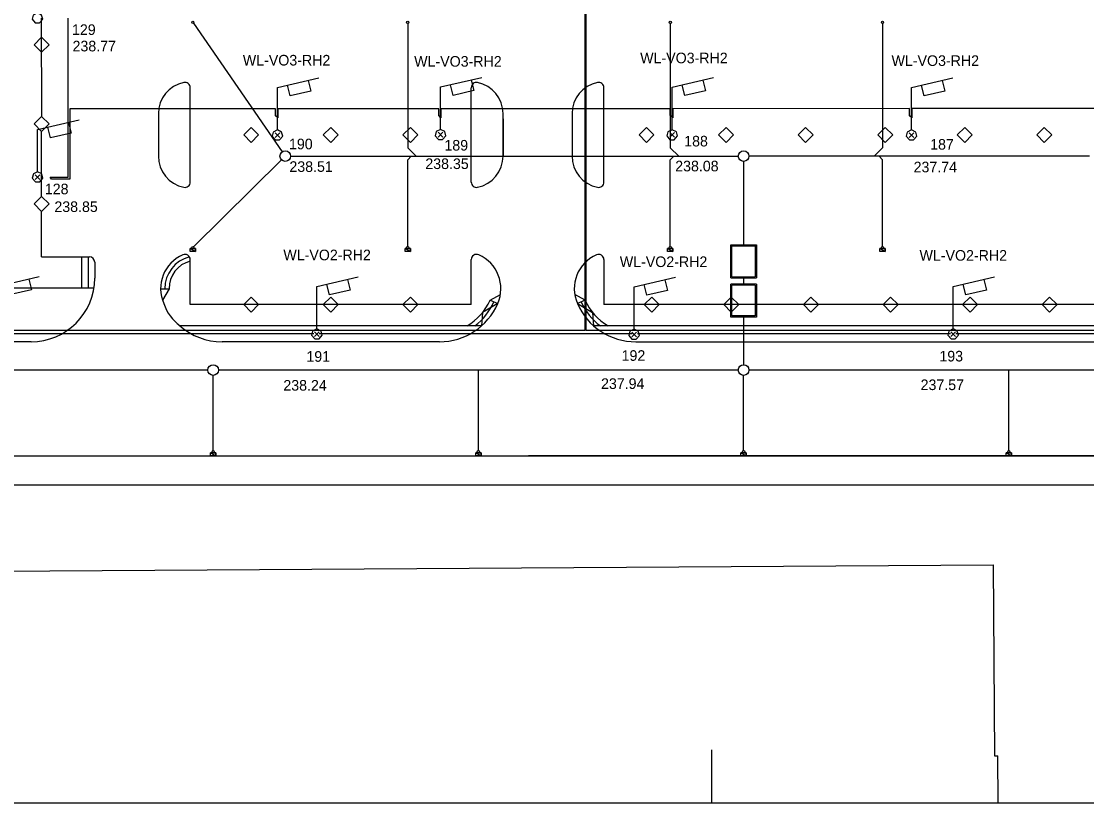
# Model space of a CAD drawing. Extents: x -264222 to -263592, y -1242345 to -1242048.
# Drawn here: x -263972 to -263871.6, y -1242344.9 to -1242271.3 of the extents above; entities that cross this region are included whole.
import ezdxf

# ---------------------------------------------------------------- set-up
doc = ezdxf.new("R2010")
doc.units = 0
for name, color, linetype in [('BOD_CISLO', 7, 'Continuous'), ('BOD_SYMBOL', 7, 'Continuous'), ('BOD_VYSKA', 7, 'Continuous'), ('KFA_2D_SITUACIA_DSP', 7, 'Continuous'), ('KFA_SO_62-1_VO_LAMPY_MERANE', 7, 'Continuous'), ('KFA_SO_62-1_VO_POPIS_LAMP_PROJEKT', 7, 'Continuous'), ('KFA_SO_62-1_VO_TRASA_KABLOV_PROJEKT', 7, 'Continuous'), ('RAM_NA_TLAC_1-500', 7, 'Continuous')]:
    doc.layers.add(name, color=color, linetype=linetype)

msp = doc.modelspace()

# ---------------------------------------------------------------- linework, layer by layer
at = {"layer": 'BOD_SYMBOL'}
for p, q in [((-263948.07, -1242282.23), (-263947.62, -1242281.78)), ((-263947.62, -1242282.23), (-263948.07, -1242281.78)), ((-263932.7, -1242282.19), (-263932.26, -1242281.74)), ((-263932.26, -1242282.19), (-263932.7, -1242281.74)), ((-263910.87, -1242282.21), (-263910.43, -1242281.76)), ((-263910.43, -1242282.21), (-263910.87, -1242281.76)), ((-263888.31, -1242282.23), (-263887.86, -1242281.79)), ((-263887.86, -1242282.23), (-263888.31, -1242281.79)), ((-263970.67, -1242286.19), (-263970.23, -1242285.74)), ((-263970.23, -1242286.19), (-263970.67, -1242285.74)), ((-263944.35, -1242300.99), (-263943.91, -1242300.55)), ((-263943.91, -1242300.99), (-263944.35, -1242300.55)), ((-263914.46, -1242301.01), (-263914.01, -1242300.57)), ((-263914.01, -1242301.01), (-263914.46, -1242300.57)), ((-263884.39, -1242300.99), (-263883.94, -1242300.55)), ((-263883.94, -1242300.99), (-263884.39, -1242300.55))]:
    msp.add_line(p, q, dxfattribs=at)
at = {"layer": 'KFA_2D_SITUACIA_DSP'}
for p, q in [((-263970.06, -1242280.24), (-263970.07, -1242270.98)), ((-263955.76, -1242271.45), (-263947.39, -1242283.57)), ((-263935.57, -1242271.47), (-263935.57, -1242283.19)), ((-263910.82, -1242271.47), (-263910.82, -1242283.19)), ((-263890.82, -1242271.47), (-263890.82, -1242283.19)), ((-263956.07, -1242286.43), (-263956.07, -1242277.53)), ((-263929.58, -1242286.43), (-263929.58, -1242277.53)), ((-263917.08, -1242286.43), (-263917.08, -1242277.53)), ((-263959.07, -1242279.98), (-263959.07, -1242283.98)), ((-263926.58, -1242283.98), (-263926.58, -1242279.98)), ((-263926.58, -1242280.48), (-263926.58, -1242283.98)), ((-263920.08, -1242279.98), (-263920.08, -1242283.98)), ((-263970.07, -1242287.78), (-263970.07, -1242281.65)), ((-263935.57, -1242283.19), (-263934.78, -1242283.98)), ((-263910.82, -1242283.19), (-263910.03, -1242283.98)), ((-263890.82, -1242283.19), (-263891.62, -1242283.98)), ((-263955.75, -1242292.52), (-263947.46, -1242284.33)), ((-263946.61, -1242283.98), (-263908.96, -1242283.98)), ((-263946.61, -1242283.98), (-263904.41, -1242283.98)), ((-263935.57, -1242284.34), (-263935.25, -1242283.98)), ((-263935.57, -1242292.49), (-263935.57, -1242284.34)), ((-263910.82, -1242284.34), (-263910.5, -1242283.98)), ((-263910.82, -1242292.49), (-263910.82, -1242284.34)), ((-263903.91, -1242284.48), (-263903.91, -1242292.35)), ((-263871.32, -1242283.98), (-263903.41, -1242283.98)), ((-263890.82, -1242284.34), (-263891.15, -1242283.98)), ((-263890.82, -1242292.49), (-263890.82, -1242284.34)), ((-263970.07, -1242293.48), (-263970.07, -1242289.19)), ((-263905.11, -1242292.35), (-263902.71, -1242292.35)), ((-263905.11, -1242295.45), (-263905.11, -1242292.35)), ((-263905.01, -1242292.45), (-263902.81, -1242292.45)), ((-263905.01, -1242295.35), (-263905.01, -1242292.45)), ((-263902.81, -1242292.45), (-263902.81, -1242295.35)), ((-263902.71, -1242292.35), (-263902.71, -1242295.45)), ((-263970.07, -1242293.48), (-263965.57, -1242293.48)), ((-263966.31, -1242293.48), (-263966.31, -1242296.43)), ((-263965.68, -1242293.48), (-263965.68, -1242296.43)), ((-263956.07, -1242292.69), (-263955.57, -1242292.69)), ((-263956.07, -1242292.98), (-263956.07, -1242292.69)), ((-263956.07, -1242292.69), (-263955.57, -1242292.98)), ((-263956.07, -1242292.69), (-263955.57, -1242292.98)), ((-263955.57, -1242292.69), (-263956.07, -1242292.69)), ((-263955.57, -1242292.98), (-263956.07, -1242292.98)), ((-263955.57, -1242292.69), (-263955.57, -1242292.98)), ((-263955.57, -1242292.98), (-263955.57, -1242292.69)), ((-263935.82, -1242292.69), (-263935.32, -1242292.69)), ((-263935.82, -1242292.98), (-263935.82, -1242292.69)), ((-263935.82, -1242292.69), (-263935.32, -1242292.98)), ((-263935.82, -1242292.69), (-263935.32, -1242292.98)), ((-263935.32, -1242292.69), (-263935.82, -1242292.69)), ((-263935.32, -1242292.98), (-263935.82, -1242292.98)), ((-263935.32, -1242292.69), (-263935.32, -1242292.98)), ((-263935.32, -1242292.98), (-263935.32, -1242292.69)), ((-263911.07, -1242292.69), (-263910.57, -1242292.69)), ((-263911.07, -1242292.98), (-263911.07, -1242292.69)), ((-263911.07, -1242292.69), (-263910.57, -1242292.98)), ((-263911.07, -1242292.69), (-263910.57, -1242292.98)), ((-263910.57, -1242292.69), (-263911.07, -1242292.69)), ((-263910.57, -1242292.98), (-263911.07, -1242292.98)), ((-263910.57, -1242292.69), (-263910.57, -1242292.98)), ((-263910.57, -1242292.98), (-263910.57, -1242292.69)), ((-263891.07, -1242292.69), (-263890.57, -1242292.69)), ((-263891.07, -1242292.98), (-263891.07, -1242292.69)), ((-263891.07, -1242292.69), (-263890.57, -1242292.98)), ((-263891.07, -1242292.69), (-263890.57, -1242292.98)), ((-263890.57, -1242292.69), (-263891.07, -1242292.69)), ((-263890.57, -1242292.98), (-263891.07, -1242292.98)), ((-263890.57, -1242292.69), (-263890.57, -1242292.98)), ((-263890.57, -1242292.98), (-263890.57, -1242292.69)), ((-263965.07, -1242293.98), (-263965.07, -1242295.48)), ((-263956.07, -1242297.98), (-263956.07, -1242293.74)), ((-263929.58, -1242297.98), (-263929.58, -1242293.74)), ((-263917.08, -1242293.74), (-263917.08, -1242297.98)), ((-263905.11, -1242295.45), (-263902.71, -1242295.45)), ((-263905.01, -1242295.35), (-263902.81, -1242295.35)), ((-263903.91, -1242295.45), (-263903.91, -1242296.05)), ((-263905.11, -1242299.15), (-263905.11, -1242296.05)), ((-263902.71, -1242296.05), (-263905.11, -1242296.05)), ((-263902.81, -1242296.15), (-263905.01, -1242296.15)), ((-263905.01, -1242299.05), (-263905.01, -1242296.15)), ((-263902.81, -1242296.15), (-263902.81, -1242299.05)), ((-263902.71, -1242296.05), (-263902.71, -1242299.15)), ((-263927.81, -1242297.56), (-263926.83, -1242297.03)), ((-263918.85, -1242297.56), (-263919.83, -1242297.03)), ((-263929.58, -1242297.98), (-263956.07, -1242297.98)), ((-263927.81, -1242297.56), (-263927.08, -1242297.88)), ((-263918.85, -1242297.56), (-263919.58, -1242297.88)), ((-263815.6, -1242297.98), (-263917.08, -1242297.98)), ((-263902.71, -1242299.15), (-263905.11, -1242299.15)), ((-263902.81, -1242299.05), (-263905.01, -1242299.05)), ((-263903.91, -1242299.15), (-263903.91, -1242303.65)), ((-263928.61, -1242299.98), (-263957.04, -1242299.98)), ((-263816.31, -1242299.98), (-263918.05, -1242299.98)), ((-263971.07, -1242301.48), (-264112.96, -1242301.48)), ((-263932.58, -1242301.48), (-263953.07, -1242301.48)), ((-263914.08, -1242301.48), (-263815.82, -1242301.48)), ((-263954.41, -1242304.15), (-264003.4, -1242304.15)), ((-263904.41, -1242304.15), (-263953.41, -1242304.15)), ((-263928.91, -1242311.74), (-263928.91, -1242304.15)), ((-263854.41, -1242304.15), (-263903.41, -1242304.15)), ((-263878.91, -1242311.74), (-263878.91, -1242304.15)), ((-263953.91, -1242311.74), (-263953.91, -1242304.65)), ((-263903.91, -1242311.74), (-263903.91, -1242304.65)), ((-263980.94, -1242312.23), (-263857.33, -1242312.23)), ((-263954.16, -1242311.94), (-263953.66, -1242311.94)), ((-263954.16, -1242312.23), (-263954.16, -1242311.94)), ((-263954.16, -1242311.94), (-263953.66, -1242312.23)), ((-263954.16, -1242311.94), (-263953.66, -1242312.23)), ((-263953.66, -1242311.94), (-263954.16, -1242311.94)), ((-263953.66, -1242312.23), (-263954.16, -1242312.23)), ((-263953.66, -1242311.94), (-263953.66, -1242312.23)), ((-263953.66, -1242312.23), (-263953.66, -1242311.94)), ((-263929.16, -1242311.94), (-263928.66, -1242311.94)), ((-263929.16, -1242312.23), (-263929.16, -1242311.94)), ((-263929.16, -1242311.94), (-263928.66, -1242312.23)), ((-263929.16, -1242311.94), (-263928.66, -1242312.23)), ((-263928.66, -1242311.94), (-263929.16, -1242311.94)), ((-263928.66, -1242312.23), (-263929.16, -1242312.23)), ((-263928.66, -1242311.94), (-263928.66, -1242312.23)), ((-263928.66, -1242312.23), (-263928.66, -1242311.94)), ((-263842.6, -1242312.24), (-263924.19, -1242312.23)), ((-263904.16, -1242311.94), (-263903.66, -1242311.94)), ((-263904.16, -1242312.23), (-263904.16, -1242311.94)), ((-263904.16, -1242311.94), (-263903.66, -1242312.23)), ((-263904.16, -1242311.94), (-263903.66, -1242312.23)), ((-263903.66, -1242311.94), (-263904.16, -1242311.94)), ((-263903.66, -1242312.23), (-263904.16, -1242312.23)), ((-263903.66, -1242311.94), (-263903.66, -1242312.23)), ((-263903.66, -1242312.23), (-263903.66, -1242311.94)), ((-263879.16, -1242311.94), (-263878.66, -1242311.94)), ((-263879.16, -1242312.23), (-263879.16, -1242311.94)), ((-263879.16, -1242311.94), (-263878.66, -1242312.23)), ((-263879.16, -1242311.94), (-263878.66, -1242312.23)), ((-263878.66, -1242311.94), (-263879.16, -1242311.94)), ((-263878.66, -1242312.23), (-263879.16, -1242312.23)), ((-263878.66, -1242311.94), (-263878.66, -1242312.23)), ((-263878.66, -1242312.23), (-263878.66, -1242311.94)), ((-264038.44, -1242314.98), (-263836.4, -1242314.98)), ((-263976.89, -1242323.14), (-263880.39, -1242322.51)), ((-263880.39, -1242322.51), (-263880.27, -1242340.53)), ((-263880.27, -1242340.53), (-263879.95, -1242340.53)), ((-263879.92, -1242344.94), (-263879.95, -1242340.53))]:
    msp.add_line(p, q, dxfattribs=at)
for points in [[(-263970.07, -1242272.78), (-263969.36, -1242273.48), (-263970.07, -1242274.19), (-263970.77, -1242273.48)], [(-263970.07, -1242280.24), (-263969.36, -1242280.94), (-263970.07, -1242281.65), (-263970.77, -1242280.94)], [(-263950.32, -1242281.28), (-263949.62, -1242281.98), (-263950.32, -1242282.69), (-263951.03, -1242281.98)], [(-263942.82, -1242281.28), (-263942.12, -1242281.98), (-263942.82, -1242282.69), (-263943.53, -1242281.98)], [(-263935.32, -1242281.28), (-263934.62, -1242281.98), (-263935.32, -1242282.69), (-263936.03, -1242281.98)], [(-263913.07, -1242281.28), (-263912.36, -1242281.98), (-263913.07, -1242282.69), (-263913.77, -1242281.98)], [(-263905.57, -1242281.28), (-263904.86, -1242281.98), (-263905.57, -1242282.69), (-263906.27, -1242281.98)], [(-263898.07, -1242281.28), (-263897.36, -1242281.98), (-263898.07, -1242282.69), (-263898.77, -1242281.98)], [(-263890.57, -1242281.28), (-263889.86, -1242281.98), (-263890.57, -1242282.69), (-263891.27, -1242281.98)], [(-263890.57, -1242281.28), (-263889.86, -1242281.98), (-263890.57, -1242282.69), (-263891.27, -1242281.98)], [(-263883.07, -1242281.28), (-263882.36, -1242281.98), (-263883.07, -1242282.69), (-263883.77, -1242281.98)], [(-263875.57, -1242281.28), (-263874.86, -1242281.98), (-263875.57, -1242282.69), (-263876.27, -1242281.98)], [(-263970.07, -1242287.78), (-263969.36, -1242288.48), (-263970.07, -1242289.19), (-263970.77, -1242288.48)], [(-263949.62, -1242297.98), (-263950.32, -1242297.28), (-263951.03, -1242297.98), (-263950.32, -1242298.69)], [(-263942.12, -1242297.98), (-263942.82, -1242297.28), (-263943.53, -1242297.98), (-263942.82, -1242298.69)], [(-263934.62, -1242297.98), (-263935.32, -1242297.28), (-263936.03, -1242297.98), (-263935.32, -1242298.69)], [(-263912.57, -1242297.28), (-263911.86, -1242297.98), (-263912.57, -1242298.69), (-263913.27, -1242297.98)], [(-263905.07, -1242297.28), (-263904.36, -1242297.98), (-263905.07, -1242298.69), (-263905.77, -1242297.98)], [(-263897.57, -1242297.28), (-263896.86, -1242297.98), (-263897.57, -1242298.69), (-263898.27, -1242297.98)], [(-263890.07, -1242297.28), (-263889.36, -1242297.98), (-263890.07, -1242298.69), (-263890.77, -1242297.98)], [(-263890.07, -1242297.28), (-263889.36, -1242297.98), (-263890.07, -1242298.69), (-263890.77, -1242297.98)], [(-263882.57, -1242297.28), (-263881.86, -1242297.98), (-263882.57, -1242298.69), (-263883.27, -1242297.98)], [(-263875.07, -1242297.28), (-263874.36, -1242297.98), (-263875.07, -1242298.69), (-263875.77, -1242297.98)]]:
    msp.add_lwpolyline(points, close=True, dxfattribs=at)
for points in [[(-263965.14, -1242296.43), (-264120.02, -1242296.43), (-264120.28, -1242296.43)], [(-263958.86, -1242296.48), (-263958.06, -1242296.48), (-263958.69, -1242297.56)], [(-263927.08, -1242297.88), (-263928.51, -1242298.71), (-263928.61, -1242299.98)], [(-263919.58, -1242297.88), (-263918.15, -1242298.71), (-263918.05, -1242299.98)]]:
    msp.add_lwpolyline(points, dxfattribs=at)
for centre, radius in [((-263955.82, -1242271.37), 0.1), ((-263935.57, -1242271.37), 0.1), ((-263910.82, -1242271.37), 0.1), ((-263890.82, -1242271.37), 0.1), ((-263947.11, -1242283.98), 0.5), ((-263903.91, -1242283.98), 0.5), ((-263955.82, -1242292.59), 0.1), ((-263935.57, -1242292.59), 0.1), ((-263910.82, -1242292.59), 0.1), ((-263890.82, -1242292.59), 0.1), ((-263953.91, -1242304.15), 0.5), ((-263903.91, -1242304.15), 0.5), ((-263953.91, -1242311.84), 0.1), ((-263928.91, -1242311.84), 0.1), ((-263903.91, -1242311.84), 0.1), ((-263878.91, -1242311.84), 0.1)]:
    msp.add_circle(centre, radius, dxfattribs=at)
for centre, radius, start, end in [((-263956.07, -1242279.98), 3, 101.537, 180), ((-263956.57, -1242277.53), 0.5, 0, 101.537), ((-263929.08, -1242277.53), 0.5, 78.463, 180), ((-263929.58, -1242279.98), 3, 0, 78.463), ((-263917.08, -1242279.98), 3, 101.537, 180), ((-263917.58, -1242277.53), 0.5, 0, 101.537), ((-263956.07, -1242283.98), 3, 180, 258.463), ((-263929.58, -1242283.98), 3, 281.537, 0), ((-263917.08, -1242283.98), 3, 180, 258.463), ((-263956.57, -1242286.43), 0.5, 258.463, 0), ((-263929.08, -1242286.43), 0.5, 180, 281.537), ((-263917.58, -1242286.43), 0.5, 258.463, 0), ((-263965.57, -1242293.98), 0.5, 0, 90), ((-263955.36, -1242296.48), 3.5, 113.7599, 203.5782), ((-263955.36, -1242296.48), 3.1, 104.5457, 180), ((-263956.57, -1242293.74), 0.5, 0, 113.7599), ((-263929.08, -1242293.74), 0.5, 66.2401, 180), ((-263930.29, -1242296.48), 3.5, 336.4218, 66.2401), ((-263916.37, -1242296.48), 3.5, 113.7599, 203.5782), ((-263917.58, -1242293.74), 0.5, 0, 113.7599), ((-263955.36, -1242296.48), 2.7, 105.2176, 180), ((-263971.07, -1242295.48), 6, 270, 0), ((-263954.44, -1242296.49), 4.35, 198.7173, 233.4513), ((-263932.58, -1242295.48), 6, 270, 336.4218), ((-263932.58, -1242295.48), 5.2, 300.0733, 336.4218), ((-263932.58, -1242295.48), 5.6, 306.5275, 336.4218), ((-263914.08, -1242295.48), 6, 203.5782, 270), ((-263914.08, -1242295.48), 5.6, 203.5782, 233.4725), ((-263914.08, -1242295.48), 5.2, 203.5782, 239.9267), ((-263953.07, -1242295.48), 6, 228.5904, 270)]:
    msp.add_arc(centre, radius, start, end, dxfattribs=at)
at = {"layer": 'KFA_SO_62-1_VO_LAMPY_MERANE'}
for p, q in [((-263947.9, -1242282.01), (-263947.79, -1242282.01)), ((-263947.85, -1242282.01), (-263947.85, -1242282.01)), ((-263932.53, -1242281.96), (-263932.43, -1242281.96)), ((-263932.48, -1242281.96), (-263932.48, -1242281.96)), ((-263910.7, -1242281.99), (-263910.6, -1242281.99)), ((-263910.65, -1242281.99), (-263910.65, -1242281.99)), ((-263888.14, -1242282.01), (-263888.04, -1242282.01)), ((-263888.09, -1242282.01), (-263888.09, -1242282.01)), ((-263970.5, -1242285.96), (-263970.4, -1242285.96)), ((-263970.45, -1242285.96), (-263970.45, -1242285.96)), ((-263944.18, -1242300.77), (-263944.08, -1242300.77)), ((-263944.13, -1242300.77), (-263944.13, -1242300.77)), ((-263914.29, -1242300.79), (-263914.19, -1242300.79)), ((-263914.24, -1242300.79), (-263914.24, -1242300.79)), ((-263884.22, -1242300.77), (-263884.11, -1242300.77)), ((-263884.16, -1242300.77), (-263884.16, -1242300.77))]:
    msp.add_line(p, q, dxfattribs=at)
for points in [[(-263970.47, -1242270.48), (-263970.87, -1242270.68), (-263970.97, -1242271.08), (-263970.67, -1242271.43), (-263970.27, -1242271.43), (-263969.97, -1242271.08), (-263970.07, -1242270.68), (-263970.47, -1242270.48), (-263970.47, -1242266.48), (-263966.57, -1242265.58)], [(-263947.85, -1242281.51), (-263948.24, -1242281.71), (-263948.35, -1242282.1), (-263948.04, -1242282.46), (-263947.65, -1242282.46), (-263947.35, -1242282.1), (-263947.45, -1242281.71), (-263947.85, -1242281.51), (-263947.85, -1242277.51), (-263943.95, -1242276.6)], [(-263944.95, -1242276.85), (-263944.7, -1242277.85), (-263946.65, -1242278.3), (-263946.9, -1242277.3)], [(-263932.48, -1242281.46), (-263932.88, -1242281.66), (-263932.98, -1242282.06), (-263932.68, -1242282.41), (-263932.28, -1242282.41), (-263931.98, -1242282.06), (-263932.08, -1242281.66), (-263932.48, -1242281.46), (-263932.48, -1242277.46), (-263928.58, -1242276.56)], [(-263929.58, -1242276.81), (-263929.33, -1242277.81), (-263931.28, -1242278.26), (-263931.53, -1242277.26)], [(-263910.65, -1242281.49), (-263911.05, -1242281.69), (-263911.15, -1242282.08), (-263910.85, -1242282.44), (-263910.45, -1242282.44), (-263910.15, -1242282.08), (-263910.25, -1242281.69), (-263910.65, -1242281.49), (-263910.65, -1242277.49), (-263906.75, -1242276.58)], [(-263907.75, -1242276.83), (-263907.5, -1242277.83), (-263909.45, -1242278.28), (-263909.7, -1242277.28)], [(-263888.09, -1242281.51), (-263888.49, -1242281.71), (-263888.59, -1242282.11), (-263888.29, -1242282.46), (-263887.89, -1242282.46), (-263887.59, -1242282.11), (-263887.69, -1242281.71), (-263888.09, -1242281.51), (-263888.09, -1242277.51), (-263884.19, -1242276.61)], [(-263885.19, -1242276.86), (-263884.94, -1242277.86), (-263886.89, -1242278.31), (-263887.14, -1242277.31)], [(-263970.45, -1242285.46), (-263970.85, -1242285.66), (-263970.95, -1242286.06), (-263970.65, -1242286.41), (-263970.25, -1242286.41), (-263969.95, -1242286.06), (-263970.05, -1242285.66), (-263970.45, -1242285.46), (-263970.45, -1242281.46), (-263966.55, -1242280.56)], [(-263967.55, -1242280.81), (-263967.3, -1242281.81), (-263969.25, -1242282.26), (-263969.5, -1242281.26)], [(-263974.19, -1242300.24), (-263974.59, -1242300.44), (-263974.69, -1242300.84), (-263974.39, -1242301.19), (-263973.99, -1242301.19), (-263973.69, -1242300.84), (-263973.79, -1242300.44), (-263974.19, -1242300.24), (-263974.19, -1242296.24), (-263970.29, -1242295.34)], [(-263944.13, -1242300.27), (-263944.53, -1242300.47), (-263944.63, -1242300.87), (-263944.33, -1242301.22), (-263943.93, -1242301.22), (-263943.63, -1242300.87), (-263943.73, -1242300.47), (-263944.13, -1242300.27), (-263944.13, -1242296.27), (-263940.23, -1242295.37)], [(-263914.24, -1242300.29), (-263914.64, -1242300.49), (-263914.74, -1242300.89), (-263914.44, -1242301.24), (-263914.04, -1242301.24), (-263913.74, -1242300.89), (-263913.84, -1242300.49), (-263914.24, -1242300.29), (-263914.24, -1242296.29), (-263910.34, -1242295.39)], [(-263884.16, -1242300.27), (-263884.57, -1242300.47), (-263884.66, -1242300.87), (-263884.36, -1242301.22), (-263883.97, -1242301.22), (-263883.66, -1242300.87), (-263883.77, -1242300.47), (-263884.16, -1242300.27), (-263884.16, -1242296.27), (-263880.27, -1242295.37)], [(-263971.29, -1242295.59), (-263971.04, -1242296.59), (-263972.99, -1242297.04), (-263973.24, -1242296.04)], [(-263941.23, -1242295.62), (-263940.98, -1242296.62), (-263942.93, -1242297.07), (-263943.18, -1242296.07)], [(-263911.34, -1242295.64), (-263911.09, -1242296.64), (-263913.04, -1242297.09), (-263913.29, -1242296.09)], [(-263881.27, -1242295.62), (-263881.02, -1242296.62), (-263882.97, -1242297.07), (-263883.22, -1242296.07)]]:
    msp.add_lwpolyline(points, dxfattribs=at)
at = {"layer": 'KFA_SO_62-1_VO_TRASA_KABLOV_PROJEKT'}
for p, q in [((-263918.84, -1242300.4), (-263918.84, -1242195.1)), ((-263918.79, -1242195.15), (-263918.79, -1242300.4)), ((-263967.57, -1242285.98), (-263967.57, -1242270.98)), ((-263888.27, -1242279.48), (-263910.57, -1242279.52)), ((-263888.27, -1242280.17), (-263888.27, -1242279.48)), ((-263864.52, -1242279.48), (-263888.07, -1242279.48)), ((-263888.07, -1242279.48), (-263888.07, -1242280.38)), ((-263948.02, -1242279.52), (-263967.4, -1242279.52)), ((-263967.4, -1242279.52), (-263967.4, -1242286.17)), ((-263948.02, -1242280.17), (-263948.02, -1242279.52)), ((-263947.82, -1242280.37), (-263948.02, -1242280.17)), ((-263932.65, -1242279.52), (-263947.82, -1242279.52)), ((-263947.82, -1242279.52), (-263947.82, -1242280.37)), ((-263932.65, -1242280.16), (-263932.65, -1242279.52)), ((-263932.45, -1242280.36), (-263932.65, -1242280.16)), ((-263910.83, -1242279.52), (-263932.45, -1242279.52)), ((-263932.45, -1242279.52), (-263932.45, -1242280.36)), ((-263910.83, -1242280.15), (-263910.83, -1242279.52)), ((-263910.57, -1242280.38), (-263910.83, -1242280.15)), ((-263910.57, -1242279.52), (-263910.57, -1242280.38)), ((-263888.07, -1242280.38), (-263888.27, -1242280.17)), ((-263969.28, -1242285.98), (-263967.57, -1242285.98)), ((-263969.13, -1242286.17), (-263969.28, -1242285.98)), ((-263967.4, -1242286.17), (-263969.13, -1242286.17)), ((-264114.14, -1242300.4), (-263918.84, -1242300.4)), ((-263918.79, -1242300.4), (-263817.94, -1242300.4)), ((-263944.42, -1242300.74), (-263973.92, -1242300.74)), ((-263914.42, -1242300.74), (-263943.92, -1242300.74)), ((-263884.42, -1242300.74), (-263913.92, -1242300.74)), ((-263854.42, -1242300.74), (-263883.92, -1242300.74))]:
    msp.add_line(p, q, dxfattribs=at)
at = {"layer": 'RAM_NA_TLAC_1-500'}
msp.add_line((-263906.9, -1242344.94), (-263906.9, -1242339.94), dxfattribs=at)
msp.add_lwpolyline([(-264221.9, -1242344.94), (-263591.9, -1242344.94), (-263591.9, -1242047.94), (-264221.9, -1242047.94)], close=True, dxfattribs=at)

# ---------------------------------------------------------------- texts
at = {"layer": 'BOD_CISLO'}
for s, p in [('129', (-263967.21, -1242272.56)), ('190', (-263946.76, -1242283.34)), ('189', (-263932.11, -1242283.46)), ('188', (-263909.51, -1242283.07)), ('187', (-263886.33, -1242283.37)), ('128', (-263969.77, -1242287.58)), ('191', (-263945.12, -1242303.37)), ('192', (-263915.41, -1242303.28)), ('193', (-263885.46, -1242303.34))]:
    msp.add_text(s, height=1, dxfattribs=at).set_placement(p)
at = {"layer": 'BOD_VYSKA'}
for s, p in [('238.77', (-263967.16, -1242274.11)), ('238.51', (-263946.72, -1242285.47)), ('238.35', (-263933.91, -1242285.2)), ('238.08', (-263910.36, -1242285.42)), ('237.74', (-263887.89, -1242285.51)), ('238.85', (-263968.87, -1242289.25)), ('238.24', (-263947.29, -1242306.09)), ('237.94', (-263917.35, -1242305.93)), ('237.57', (-263887.23, -1242306.04))]:
    msp.add_text(s, height=1, dxfattribs=at).set_placement(p)
at = {"layer": 'KFA_SO_62-1_VO_POPIS_LAMP_PROJEKT'}
for s, p in [('WL-VO3-RH2', (-263951.11, -1242275.44)), ('WL-VO3-RH2', (-263913.66, -1242275.23)), ('WL-VO3-RH2', (-263934.96, -1242275.55)), ('WL-VO3-RH2', (-263889.97, -1242275.48)), ('WL-VO2-RH2', (-263947.29, -1242293.8)), ('WL-VO2-RH2', (-263915.58, -1242294.44)), ('WL-VO2-RH2', (-263887.33, -1242293.84))]:
    msp.add_text(s, height=1, dxfattribs=at).set_placement(p)

doc.saveas('drawing.dxf')
